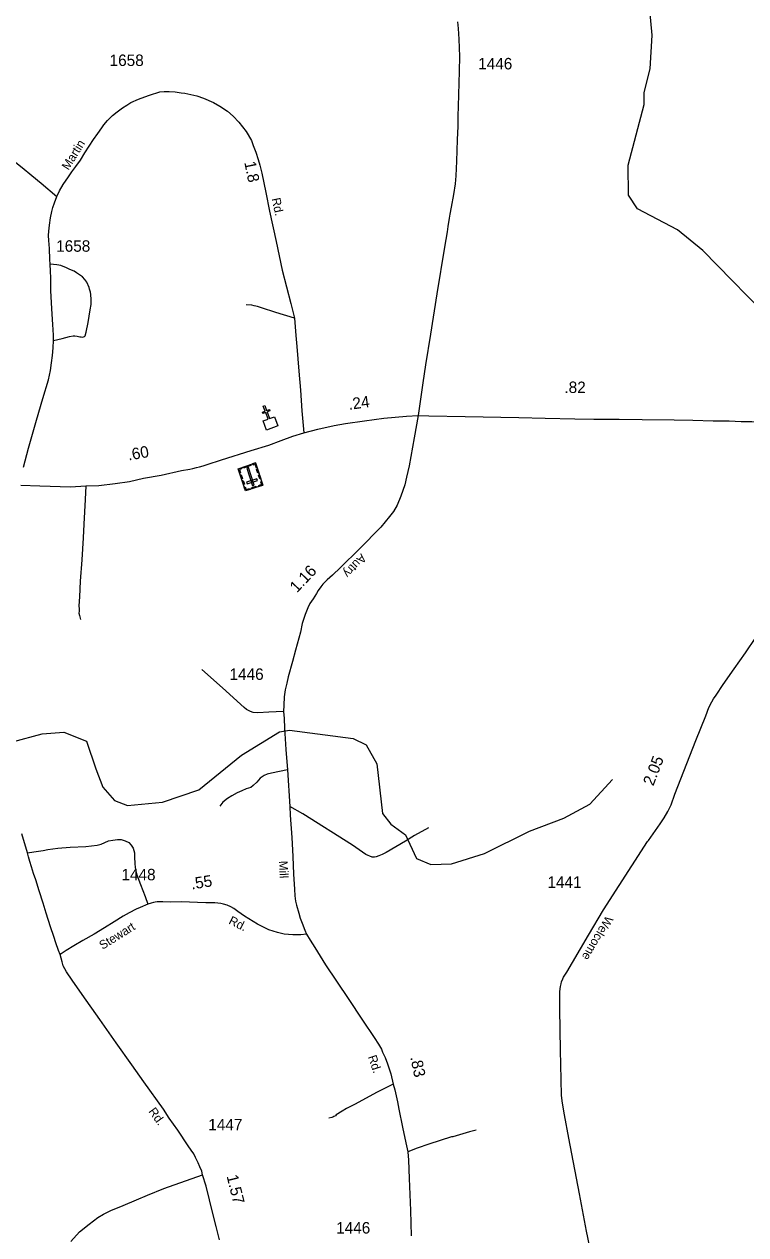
# Model space of a CAD drawing. Extents: x 2093524 to 2270757, y 289120 to 570408.
# Drawn here: x 2110673 to 2118532, y 503417 to 516601 of the extents above; entities that cross this region are included whole.
import ezdxf

# ---------------------------------------------------------------- set-up
doc = ezdxf.new("R2010")
doc.units = 0
for name, color, linetype in [('Exist Cultural Cemetery CELL', 7, 'Continuous'), ('Exist Cultural Church CELL', 7, 'Continuous'), ('Exist Hydrographic Creek Single Shore', 7, 'Continuous'), ('Exist Hydrographic Misc Water Feature', 7, 'Continuous'), ('Exist Road Non-System Type 51', 7, 'Continuous'), ('Exist Road Primary US Attributed', 7, 'Continuous'), ('Exist Road Primary US Mileage Hundredths English Label', 7, 'Continuous'), ('Exist Road Secondary Mileage Hundredths English Label', 7, 'Continuous'), ('Exist Road Secondary Type 51 Attributed', 7, 'Continuous'), ('Exist Road Secondary Type 51 Label', 7, 'Continuous'), ('Exist Road Secondary Type 51 Number Label', 7, 'Continuous')]:
    doc.layers.add(name, color=color, linetype=linetype)

msp = doc.modelspace()

# ---------------------------------------------------------------- linework, layer by layer
at = {"layer": 'Exist Cultural Cemetery CELL'}
for points in [[(2113273, 511581), (2113084, 511518), (2113004, 511760), (2113193, 511823)], [(2113035, 511771), (2113039, 511760), (2113018, 511753), (2113030, 511714), (2113020, 511711), (2113004, 511760)], [(2113142, 511794), (2113061, 511767), (2113058, 511778), (2113138, 511805)], [(2113160, 511575), (2113178, 511580), (2113114, 511773), (2113096, 511767)], [(2113161, 511812), (2113165, 511801), (2113186, 511808), (2113198, 511770), (2113209, 511773), (2113193, 511823)], [(2113215, 511756), (2113228, 511715), (2113217, 511712), (2113204, 511753)], [(2113037, 511695), (2113051, 511654), (2113040, 511650), (2113026, 511692)], [(2113058, 511633), (2113071, 511591), (2113061, 511588), (2113047, 511629)], [(2113212, 511633), (2113207, 511650), (2113095, 511613), (2113101, 511596)], [(2113202, 511558), (2113153, 511541), (2113149, 511552), (2113199, 511569)], [(2113259, 511622), (2113248, 511618), (2113258, 511588), (2113220, 511575), (2113223, 511565), (2113273, 511581)], [(2113236, 511692), (2113249, 511651), (2113238, 511648), (2113225, 511689)], [(2113070, 511560), (2113081, 511563), (2113091, 511533), (2113129, 511545), (2113133, 511535), (2113083, 511518)]]:
    msp.add_lwpolyline(points, close=True, dxfattribs=at)
at = {"layer": 'Exist Cultural Church CELL'}
msp.add_lwpolyline([(2113276, 512281), (2113330, 512301), (2113303, 512372), (2113273, 512361), (2113268, 512376), (2113298, 512387), (2113277, 512443), (2113292, 512449), (2113313, 512393), (2113343, 512404), (2113348, 512389), (2113318, 512378), (2113345, 512306), (2113399, 512326), (2113436, 512226), (2113313, 512181)], close=True, dxfattribs=at)
at = {"layer": 'Exist Hydrographic Creek Single Shore'}
msp.add_lwpolyline([(2118868, 513315), (2118064, 514135), (2117788, 514360), (2117354, 514592), (2117254, 514741), (2117252, 515066), (2117424, 515725), (2117424, 515857), (2117489, 516114), (2117512, 516481), (2117442, 517224), (2117438, 518274), (2117278, 518697), (2117059, 519171)], dxfattribs=at)
at = {"layer": 'Exist Hydrographic Misc Water Feature'}
for points in [[(2109228, 506376), (2109303, 506601), (2109626, 506952), (2109851, 507069), (2109934, 507202), (2109958, 507336), (2109866, 507702), (2109881, 508145), (2109938, 508360), (2110163, 508605), (2110545, 508787), (2110870, 508873), (2111103, 508891), (2111353, 508791), (2111454, 508490), (2111530, 508292), (2111655, 508148), (2111797, 508093), (2112180, 508128)], [(2112180, 508128), (2112575, 508264), (2113040, 508639), (2113455, 508893), (2113563, 508911), (2114255, 508821), (2114397, 508753), (2114515, 508547), (2114576, 508004), (2114667, 507888), (2114826, 507773), (2114944, 507515), (2115103, 507449), (2115328, 507458), (2115685, 507569), (2116176, 507812), (2116550, 507955), (2116833, 508107), (2117081, 508374)]]:
    msp.add_lwpolyline(points, dxfattribs=at)
at = {"layer": 'Exist Road Non-System Type 51'}
for points in [[(2110178, 515684), (2110166, 515601), (2110162, 515573), (2110157, 515543), (2110159, 515517), (2110168, 515493), (2110190, 515460), (2110241, 515415), (2110333, 515329), (2110349, 515311), (2110405, 515252), (2110439, 515209), (2110482, 515166), (2110545, 515123), (2110649, 515041), (2110757, 514953), (2110856, 514871), (2111029, 514725)], [(2110993, 513158), (2111086, 513178), (2111168, 513201), (2111206, 513208), (2111226, 513207), (2111248, 513203), (2111278, 513198), (2111294, 513196), (2111310, 513194), (2111320, 513196), (2111328, 513201), (2111336, 513209), (2111347, 513247), (2111371, 513353), (2111392, 513490), (2111401, 513550), (2111402, 513578), (2111402, 513602), (2111399, 513656), (2111394, 513682), (2111384, 513714), (2111379, 513734), (2111354, 513791), (2111335, 513819), (2111307, 513848), (2111242, 513895), (2111216, 513910), (2111171, 513931), (2111133, 513947), (2111072, 513972), (2111030, 513979), (2110954, 513989)], [(2113617, 513399), (2113412, 513463), (2113257, 513512), (2113213, 513525), (2113176, 513535), (2113152, 513540), (2113092, 513545)], [(2111343, 511573), (2111336, 511425), (2111321, 511156), (2111314, 511006), (2111301, 510768), (2111284, 510534), (2111277, 510365), (2111269, 510267), (2111270, 510235), (2111270, 510209), (2111269, 510185), (2111277, 510161), (2111286, 510118)], [(2113497, 509115), (2113339, 509109), (2113217, 509103), (2113167, 509106), (2113137, 509115), (2113095, 509136), (2113068, 509160), (2112832, 509375), (2112608, 509573)], [(2113540, 508479), (2113365, 508444), (2113319, 508433), (2113287, 508418), (2113242, 508389), (2113207, 508347), (2113167, 508310), (2113140, 508289), (2113090, 508272), (2113043, 508253), (2112991, 508230), (2112936, 508197), (2112886, 508168), (2112837, 508129), (2112802, 508086)], [(2115077, 507848), (2114923, 507765), (2114824, 507705), (2114616, 507581), (2114571, 507558), (2114537, 507543), (2114507, 507533), (2114489, 507530), (2114461, 507530), (2114393, 507558), (2114247, 507661), (2113708, 508001), (2113566, 508082)], [(2110709, 507576), (2110777, 507589), (2110880, 507603), (2110932, 507612), (2111040, 507626), (2111172, 507637), (2111344, 507645), (2111467, 507661), (2111511, 507670), (2111590, 507708), (2111640, 507715), (2111690, 507722), (2111728, 507720), (2111774, 507707), (2111811, 507688), (2111837, 507659), (2111858, 507627), (2111873, 507575), (2111876, 507529), (2111879, 507461), (2111882, 507417), (2111889, 507376), (2111898, 507338), (2111938, 507231), (2111989, 507100), (2112020, 507016)], [(2114693, 505058), (2114509, 504966), (2114279, 504840), (2114182, 504792), (2114135, 504763), (2114072, 504722), (2114062, 504713), (2114044, 504705), (2114036, 504699), (2114022, 504693), (2113990, 504686)], [(2115597, 504556), (2115522, 504537), (2115341, 504485), (2115327, 504483), (2115080, 504404), (2114951, 504361), (2114850, 504319)], [(2111180, 503343), (2111274, 503447), (2111380, 503531), (2111475, 503603), (2111536, 503642), (2111617, 503682), (2111750, 503737), (2111895, 503799), (2112014, 503848), (2112194, 503920), (2112615, 504070)]]:
    msp.add_lwpolyline(points, dxfattribs=at)
at = {"layer": 'Exist Road Primary US Attributed'}
for points in [[(2113718, 512149), (2113871, 512192), (2114049, 512230), (2114172, 512254), (2114380, 512283), (2114591, 512311), (2114837, 512332), (2114963, 512340)], [(2114963, 512340), (2115081, 512337), (2115477, 512329), (2116061, 512316), (2116347, 512312), (2116671, 512303), (2116878, 512301), (2117154, 512300), (2117402, 512295), (2117752, 512292), (2117954, 512289), (2118176, 512283), (2118350, 512280), (2118482, 512275), (2118596, 512275), (2118898, 512265), (2119266, 512253)], [(2110637, 511582), (2110844, 511572), (2111177, 511563), (2111343, 511573), (2111487, 511578), (2111664, 511599), (2111820, 511622), (2111971, 511657), (2112165, 511690), (2112386, 511740), (2112476, 511754), (2112508, 511761), (2112548, 511772), (2112582, 511782), (2112621, 511793), (2112667, 511806), (2112820, 511857), (2113146, 511960), (2113337, 512018), (2113470, 512068), (2113599, 512113), (2113718, 512149)]]:
    msp.add_lwpolyline(points, dxfattribs=at)
at = {"layer": 'Exist Road Secondary Type 51 Attributed'}
for points in [[(2115392, 516628), (2115398, 516556), (2115406, 516440), (2115414, 516248), (2115411, 516090), (2115408, 515958), (2115404, 515834), (2115399, 515704), (2115395, 515603), (2115397, 515491), (2115390, 515341), (2115381, 515111), (2115374, 514951), (2115368, 514861), (2115350, 514748), (2115323, 514610), (2115310, 514534), (2115303, 514489), (2115287, 514399), (2115280, 514339), (2115252, 514174), (2115168, 513663), (2115097, 513227), (2115043, 512890), (2115013, 512697), (2114963, 512340)], [(2110665, 511777), (2110720, 511982), (2110808, 512290), (2110876, 512523), (2110937, 512727), (2110959, 512829), (2110970, 512913), (2110982, 512994), (2110990, 513076), (2110993, 513158), (2110992, 513214), (2110985, 513332), (2110974, 513500), (2110964, 513701), (2110963, 513839), (2110958, 513911), (2110954, 513989), (2110953, 514039), (2110949, 514157), (2110943, 514245), (2110938, 514301), (2110941, 514347), (2110947, 514413), (2110958, 514491), (2110973, 514560), (2110986, 514606), (2111003, 514654), (2111029, 514725), (2111058, 514785), (2111097, 514854), (2111155, 514939), (2111192, 514994), (2111235, 515051), (2111285, 515122), (2111332, 515199), (2111429, 515345), (2111475, 515412), (2111518, 515473), (2111542, 515507), (2111581, 515552), (2111634, 515607), (2111685, 515648), (2111744, 515691), (2111789, 515720), (2111835, 515749), (2111918, 515783), (2111987, 515812), (2112037, 515827), (2112149, 515863), (2112197, 515868), (2112220, 515868)], [(2112220, 515868), (2112251, 515868), (2112318, 515863), (2112384, 515853), (2112424, 515850), (2112488, 515837), (2112554, 515822), (2112625, 515796), (2112734, 515750), (2112805, 515707), (2112886, 515653), (2112947, 515600), (2113010, 515535), (2113092, 515431), (2113148, 515336), (2113167, 515279), (2113195, 515207), (2113222, 515128), (2113240, 515066), (2113261, 514980), (2113304, 514767), (2113346, 514564), (2113416, 514236), (2113481, 513923), (2113578, 513561), (2113617, 513399), (2113633, 513212), (2113643, 513092), (2113663, 512824), (2113681, 512617), (2113695, 512391), (2113718, 512149)], [(2114963, 512340), (2114921, 512096), (2114864, 511790), (2114838, 511668), (2114818, 511583), (2114774, 511462), (2114736, 511362), (2114696, 511295), (2114651, 511238), (2114557, 511124), (2114324, 510889), (2114118, 510685), (2114031, 510601), (2113972, 510550), (2113927, 510503), (2113902, 510473), (2113875, 510434), (2113855, 510402), (2113821, 510343), (2113782, 510292), (2113761, 510246), (2113732, 510173), (2113702, 510073), (2113682, 509978), (2113628, 509783), (2113596, 509659), (2113548, 509492), (2113533, 509425), (2113516, 509353), (2113506, 509277), (2113502, 509183), (2113497, 509115), (2113503, 509039), (2113509, 508935), (2113524, 508703), (2113540, 508479), (2113566, 508082), (2113570, 507988), (2113589, 507742), (2113597, 507536), (2113607, 507345), (2113616, 507181), (2113620, 507107), (2113629, 507051), (2113640, 507007), (2113663, 506920), (2113677, 506866), (2113700, 506810), (2113731, 506735), (2113746, 506691)], [(2116881, 503058), (2116797, 503456), (2116721, 503861), (2116603, 504470), (2116556, 504722), (2116537, 504849), (2116526, 504933), (2116522, 505109), (2116512, 505429), (2116507, 505873), (2116507, 506065), (2116512, 506121), (2116521, 506149), (2116525, 506171), (2116538, 506203), (2116548, 506224), (2116581, 506278), (2116643, 506383), (2116819, 506681), (2116983, 506954), (2117462, 507700), (2117472, 507710), (2117598, 507891), (2117643, 507958), (2117682, 508027), (2117718, 508099), (2117760, 508214), (2117988, 508801), (2118095, 509069), (2118131, 509160), (2118162, 509220), (2118181, 509255), (2118208, 509295), (2118286, 509409), (2118404, 509581), (2118527, 509754), (2118642, 509922)], [(2111063, 506469), (2111046, 506513), (2111017, 506598), (2110997, 506666), (2110961, 506769), (2110914, 506918), (2110880, 507027), (2110837, 507164), (2110799, 507282), (2110776, 507351), (2110752, 507425), (2110735, 507482), (2110720, 507534), (2110709, 507576), (2110647, 507785)], [(2113746, 506691), (2113686, 506684), (2113598, 506684), (2113550, 506687), (2113504, 506692), (2113432, 506707), (2113337, 506737), (2113212, 506799), (2113074, 506888), (2112999, 506938), (2112956, 506971), (2112922, 506987), (2112884, 507006), (2112845, 507017), (2112813, 507023), (2112749, 507031), (2112651, 507031), (2112383, 507042), (2112265, 507040), (2112182, 507043), (2112146, 507043), (2112122, 507042), (2112100, 507038), (2112080, 507035), (2112054, 507027), (2112020, 507016), (2111937, 506982), (2111893, 506964), (2111816, 506922), (2111751, 506887), (2111652, 506825), (2111547, 506761), (2111435, 506690), (2111310, 506620), (2111213, 506562), (2111130, 506514), (2111063, 506469)], [(2113746, 506691), (2113789, 506624), (2113837, 506545), (2113955, 506355), (2114200, 505990), (2114359, 505755), (2114485, 505564), (2114532, 505491), (2114563, 505438), (2114576, 505406), (2114605, 505348), (2114631, 505277), (2114667, 505168), (2114693, 505058), (2114708, 504996), (2114737, 504863), (2114753, 504785), (2114792, 504590), (2114819, 504469), (2114835, 504385), (2114850, 504319), (2114858, 504231), (2114866, 504031), (2114879, 503680), (2114886, 503404)], [(2112801, 503360), (2112764, 503505), (2112729, 503648), (2112655, 503945), (2112615, 504070), (2112606, 504108), (2112587, 504158), (2112568, 504201), (2112539, 504259), (2112520, 504298), (2112491, 504338), (2112460, 504385), (2112347, 504555), (2112252, 504687), (2112191, 504785), (2111977, 505081), (2111845, 505269), (2111675, 505507), (2111496, 505760), (2111306, 506032), (2111197, 506190), (2111133, 506280), (2111098, 506346), (2111085, 506391), (2111063, 506469)]]:
    msp.add_lwpolyline(points, dxfattribs=at)

# ---------------------------------------------------------------- texts
at = {"layer": 'Exist Road Primary US Mileage Hundredths English Label'}
for s, rotation, p in [('.82', 359.6676, (2116556, 512585)), ('.24', 7.4931, (2114211, 512401)), ('.60', 9.7889, (2111810, 511849))]:
    msp.add_text(s, height=125, rotation=rotation, dxfattribs=at).set_placement(p)
at = {"layer": 'Exist Road Secondary Mileage Hundredths English Label'}
for s, rotation, p in [('1.8', 281.5996, (2113069, 515097)), ('1.16', 46.306, (2113642, 510402)), ('2.05', 68.803, (2117524, 508298)), ('.55', 9.0323, (2112498, 507177)), ('.83', 281.8302, (2114877, 505350)), ('1.57', 283.9681, (2112876, 504056))]:
    msp.add_text(s, height=125, rotation=rotation, dxfattribs=at).set_placement(p)
at = {"layer": 'Exist Road Secondary Type 51 Label'}
for s, rotation, p in [('Martin', 58.2759, (2111155, 515005)), ('Rd.', 281.6735, (2113368, 514701)), ('Autry', 226.6696, (2114342, 510842)), ('Mill', 272.1952, (2113448, 507488)), ('Rd.', 333.4369, (2112892, 506808)), ('Welcome', 239.518, (2117011, 506898)), ('Stewart', 31.9797, (2111526, 506519)), ('Rd.', 288.2298, (2114416, 505356)), ('Rd.', 305.8774, (2112022, 504760))]:
    msp.add_text(s, height=95, rotation=rotation, dxfattribs=at).set_placement(p)
at = {"layer": 'Exist Road Secondary Type 51 Number Label'}
for s, p in [('1658', (2111603, 516146)), ('1446', (2115617, 516109)), ('1658', (2111021, 514123)), ('1446', (2112909, 509460)), ('1448', (2111732, 507277)), ('1441', (2116371, 507195)), ('1447', (2112678, 504554)), ('1446', (2114070, 503430))]:
    msp.add_text(s, height=125, dxfattribs=at).set_placement(p)

doc.saveas('drawing.dxf')
